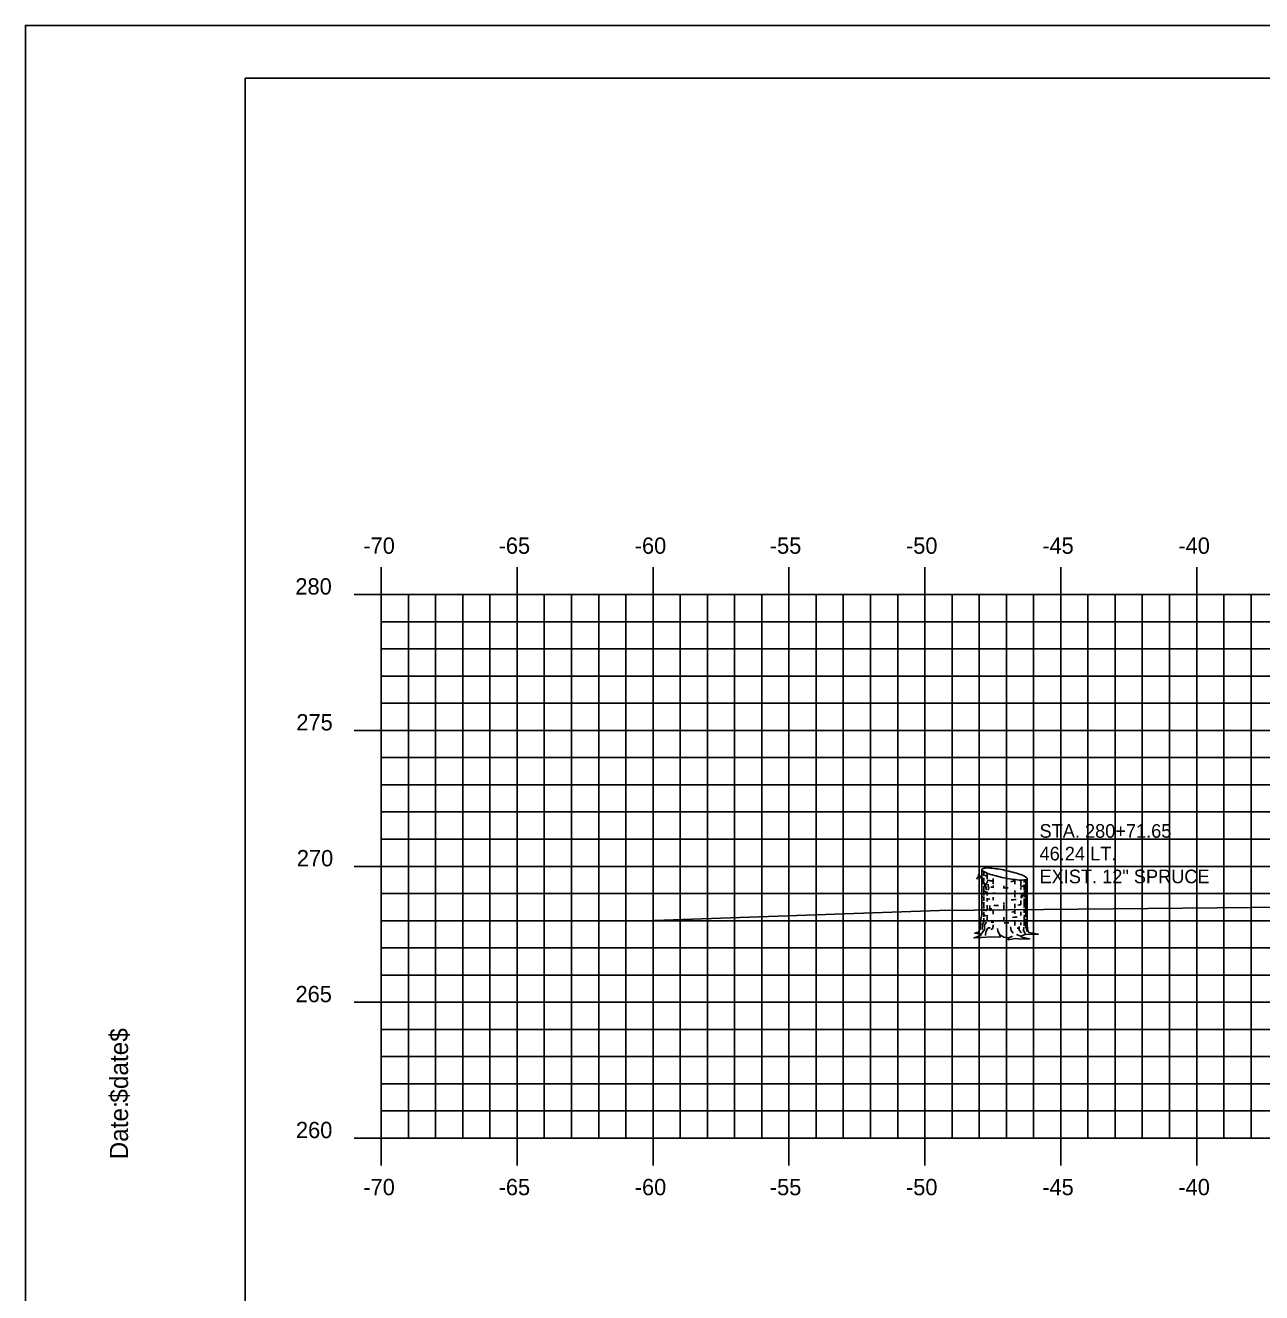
# Model space of a CAD drawing. Extents: x 855121 to 855291, y 366268 to 366378.
# Drawn here: x 855121.35 to 855166.83, y 366331.55 to 366378.18 of the extents above; entities that cross this region are included whole.
import ezdxf

# ---------------------------------------------------------------- set-up
doc = ezdxf.new("R2010")
doc.units = 0
for name, color, linetype in [('BORDER', 7, 'Continuous'), ('D_Text_Monospaced', 7, 'Continuous'), ('H_V ANNOTATION', 7, 'Continuous'), ('MAJOR', 7, 'Continuous'), ('MINOR', 7, 'Continuous'), ('PLOT BOUNDARY', 7, 'Continuous'), ('S_Roadway_Centerline', 7, 'Continuous'), ('S_Trees_Conifer_Pay', 7, 'Continuous')]:
    doc.layers.add(name, color=color, linetype=linetype)

msp = doc.modelspace()

# ---------------------------------------------------------------- linework, layer by layer
at = {"layer": 'BORDER'}
for p, q in [((855289.442, 366376.236), (855129.442, 366376.236)), ((855129.442, 366376.236), (855129.442, 366271.236))]:
    msp.add_line(p, q, dxfattribs=at)
at = {"layer": 'MAJOR'}
for p, q in [((855134.442, 366358.238), (855134.442, 366357.236)), ((855139.442, 366358.238), (855139.442, 366357.236)), ((855144.442, 366358.238), (855144.442, 366357.236)), ((855149.442, 366358.238), (855149.442, 366357.236)), ((855154.442, 366358.238), (855154.442, 366357.236)), ((855159.442, 366358.238), (855159.442, 366357.236)), ((855164.442, 366358.238), (855164.442, 366357.236)), ((855133.44, 366357.236), (855134.442, 366357.236)), ((855134.442, 366357.236), (855274.442, 366357.236)), ((855134.442, 366337.236), (855134.442, 366357.236)), ((855134.442, 366337.236), (855134.442, 366357.236)), ((855134.442, 366357.236), (855274.442, 366357.236)), ((855139.442, 366337.236), (855139.442, 366357.236)), ((855144.442, 366337.236), (855144.442, 366357.236)), ((855149.442, 366337.236), (855149.442, 366357.236)), ((855154.442, 366337.236), (855154.442, 366357.236)), ((855159.442, 366337.236), (855159.442, 366357.236)), ((855164.442, 366337.236), (855164.442, 366357.236)), ((855133.44, 366352.236), (855134.442, 366352.236)), ((855134.442, 366352.236), (855274.442, 366352.236)), ((855133.44, 366347.236), (855134.442, 366347.236)), ((855134.442, 366347.236), (855274.442, 366347.236)), ((855133.44, 366342.236), (855134.442, 366342.236)), ((855134.442, 366342.236), (855274.442, 366342.236)), ((855133.44, 366337.236), (855134.442, 366337.236)), ((855134.442, 366337.236), (855274.442, 366337.236)), ((855134.442, 366337.236), (855274.442, 366337.236)), ((855134.442, 366336.234), (855134.442, 366337.236)), ((855139.442, 366336.234), (855139.442, 366337.236)), ((855144.442, 366336.234), (855144.442, 366337.236)), ((855149.442, 366336.234), (855149.442, 366337.236)), ((855154.442, 366336.234), (855154.442, 366337.236)), ((855159.442, 366336.234), (855159.442, 366337.236)), ((855164.442, 366336.234), (855164.442, 366337.236))]:
    msp.add_line(p, q, dxfattribs=at)
at = {"layer": 'MINOR'}
for p, q in [((855135.442, 366337.236), (855135.442, 366357.236)), ((855136.442, 366337.236), (855136.442, 366357.236)), ((855137.442, 366337.236), (855137.442, 366357.236)), ((855138.442, 366337.236), (855138.442, 366357.236)), ((855140.442, 366337.236), (855140.442, 366357.236)), ((855141.442, 366337.236), (855141.442, 366357.236)), ((855142.442, 366337.236), (855142.442, 366357.236)), ((855143.442, 366337.236), (855143.442, 366357.236)), ((855145.442, 366337.236), (855145.442, 366357.236)), ((855146.442, 366337.236), (855146.442, 366357.236)), ((855147.442, 366337.236), (855147.442, 366357.236)), ((855148.442, 366337.236), (855148.442, 366357.236)), ((855150.442, 366337.236), (855150.442, 366357.236)), ((855151.442, 366337.236), (855151.442, 366357.236)), ((855152.442, 366337.236), (855152.442, 366357.236)), ((855153.442, 366337.236), (855153.442, 366357.236)), ((855155.442, 366337.236), (855155.442, 366357.236)), ((855156.442, 366337.236), (855156.442, 366357.236)), ((855157.442, 366337.236), (855157.442, 366357.236)), ((855158.442, 366337.236), (855158.442, 366357.236)), ((855160.442, 366337.236), (855160.442, 366357.236)), ((855161.442, 366337.236), (855161.442, 366357.236)), ((855162.442, 366337.236), (855162.442, 366357.236)), ((855163.442, 366337.236), (855163.442, 366357.236)), ((855165.442, 366337.236), (855165.442, 366357.236)), ((855166.442, 366337.236), (855166.442, 366357.236)), ((855134.442, 366356.236), (855274.442, 366356.236)), ((855134.442, 366356.236), (855135.444, 366356.236)), ((855134.442, 366355.236), (855274.442, 366355.236)), ((855134.442, 366355.236), (855135.444, 366355.236)), ((855134.442, 366354.236), (855274.442, 366354.236)), ((855134.442, 366354.236), (855135.444, 366354.236)), ((855134.442, 366353.236), (855274.442, 366353.236)), ((855134.442, 366353.236), (855135.444, 366353.236)), ((855134.442, 366351.236), (855274.442, 366351.236)), ((855134.442, 366351.236), (855135.444, 366351.236)), ((855134.442, 366350.236), (855274.442, 366350.236)), ((855134.442, 366350.236), (855135.444, 366350.236)), ((855134.442, 366349.236), (855274.442, 366349.236)), ((855134.442, 366349.236), (855135.444, 366349.236)), ((855134.442, 366348.236), (855135.444, 366348.236)), ((855134.442, 366348.236), (855274.442, 366348.236)), ((855134.442, 366346.236), (855274.442, 366346.236)), ((855134.442, 366346.236), (855135.444, 366346.236)), ((855134.442, 366345.236), (855274.442, 366345.236)), ((855134.442, 366345.236), (855135.444, 366345.236)), ((855134.442, 366344.236), (855274.442, 366344.236)), ((855134.442, 366344.236), (855135.444, 366344.236)), ((855134.442, 366343.236), (855274.442, 366343.236)), ((855134.442, 366343.236), (855135.444, 366343.236)), ((855134.442, 366341.236), (855274.442, 366341.236)), ((855134.442, 366341.236), (855135.444, 366341.236)), ((855134.442, 366340.236), (855274.442, 366340.236)), ((855134.442, 366340.236), (855135.444, 366340.236)), ((855134.442, 366339.236), (855274.442, 366339.236)), ((855134.442, 366339.236), (855135.444, 366339.236)), ((855134.442, 366338.236), (855274.442, 366338.236)), ((855134.442, 366338.236), (855135.444, 366338.236))]:
    msp.add_line(p, q, dxfattribs=at)
at = {"layer": 'PLOT BOUNDARY'}
msp.add_lwpolyline([(855121.349, 366268.177), (855291.349, 366268.177), (855291.349, 366378.177), (855121.349, 366378.177)], close=True, dxfattribs=at)
at = {"layer": 'S_Roadway_Centerline'}
msp.add_lwpolyline([(855144.138, 366345.236), (855154.981, 366345.612), (855167.747, 366345.731), (855178.089, 366345.883), (855179.388, 366345.897), (855182.154, 366346.026), (855184.948, 366346.054), (855186.531, 366346.008), (855186.852, 366345.93), (855188.684, 366345.832), (855189.07, 366345.851), (855194.05, 366346.181), (855199.995, 366346.43), (855204.747, 366346.643), (855214.965, 366346.488), (855215.768, 366346.474), (855220.431, 366346.316), (855220.775, 366346.323), (855220.997, 366346.289), (855221.747, 366346.285), (855225.306, 366346.406), (855236.796, 366346.885)], dxfattribs=at)
at = {"layer": 'S_Trees_Conifer_Pay'}
for p, q in [((855156.54, 366345.473), (855156.54, 366347.12)), ((855156.611, 366347.048), (855156.611, 366346.885)), ((855156.611, 366346.818), (855156.611, 366346.69)), ((855156.729, 366346.987), (855156.729, 366346.764)), ((855156.729, 366346.675), (855156.729, 366346.628)), ((855156.957, 366346.791), (855156.957, 366346.591)), ((855157.753, 366346.749), (855157.753, 366346.581)), ((855157.973, 366346.728), (855157.973, 366346.496)), ((855158.098, 366346.736), (855158.098, 366346.638)), ((855158.098, 366346.564), (855158.098, 366346.36)), ((855158.156, 366346.747), (855158.156, 366346.276)), ((855158.204, 366345.063), (855158.204, 366346.785)), ((855156.611, 366346.503), (855156.611, 366346.167)), ((855156.611, 366346.13), (855156.611, 366345.967)), ((855156.671, 366346.492), (855156.723, 366346.432)), ((855156.729, 366346.293), (855156.729, 366346.161)), ((855156.957, 366346.533), (855156.957, 366346.445)), ((855156.957, 366346.097), (855156.957, 366345.992)), ((855157.347, 366346.517), (855157.347, 366346.422)), ((855157.753, 366346.344), (855157.753, 366346.107)), ((855157.973, 366346.455), (855157.973, 366346.381)), ((855158.098, 366346.302), (855158.098, 366346.103)), ((855158.156, 366346.212), (855158.156, 366345.904)), ((855156.611, 366345.92), (855156.611, 366345.703)), ((855156.611, 366345.673), (855156.611, 366345.598)), ((855156.729, 366346.05), (855156.729, 366345.94)), ((855156.729, 366345.804), (855156.729, 366345.663)), ((855156.957, 366345.625), (855156.957, 366345.479)), ((855157.347, 366345.904), (855157.347, 366345.829)), ((855157.347, 366345.804), (855157.347, 366345.656)), ((855157.753, 366345.862), (855157.753, 366345.71)), ((855157.753, 366345.667), (855157.753, 366345.493)), ((855157.973, 366345.978), (855157.973, 366345.839)), ((855158.098, 366346.056), (855158.098, 366345.72)), ((855158.098, 366345.667), (855158.098, 366345.531)), ((855158.156, 366345.856), (855158.156, 366345.364)), ((855156.611, 366345.558), (855156.611, 366345.384)), ((855156.729, 366345.436), (855156.729, 366345.263)), ((855156.957, 366345.247), (855156.957, 366345.158)), ((855157.347, 366345.364), (855157.347, 366345.211)), ((855157.753, 366345.216), (855157.753, 366345.063)), ((855157.973, 366345.568), (855157.973, 366345.426)), ((855157.973, 366345.164), (855157.973, 366345.07)), ((855158.098, 366345.432), (855158.098, 366345.053)), ((855158.156, 366345.31), (855158.156, 366345.063)), ((855157.973, 366344.67), (855157.81, 366344.734)), ((855157.536, 366344.606), (855157.662, 366344.67))]:
    msp.add_line(p, q, dxfattribs=at)
for points in [[(855156.494, 366346.851), (855156.418, 366346.859), (855156.346, 366346.76)], [(855156.723, 366346.618), (855156.686, 366346.544), (855156.639, 366346.601), (855156.581, 366346.669), (855156.488, 366346.863), (855156.424, 366346.91), (855156.393, 366346.917)], [(855156.708, 366346.365), (855156.671, 366346.492), (855156.608, 366346.608), (855156.577, 366346.675), (855156.508, 366346.821)], [(855156.756, 366346.581), (855156.787, 366346.496), (855156.791, 366346.428), (855156.76, 366346.365)], [(855158.024, 366346.091), (855158.03, 366346.186), (855157.987, 366346.163), (855157.987, 366346.068)], [(855156.885, 366345.692), (855156.873, 366345.615), (855156.826, 366345.625), (855156.838, 366345.792)], [(855156.54, 366345.473), (855156.488, 366345.211), (855156.472, 366344.938), (855156.414, 366344.812), (855156.278, 366344.781), (855156.509, 366344.744), (855156.509, 366344.744), (855156.503, 366344.697), (855156.255, 366344.602), (855156.53, 366344.619), (855156.885, 366344.639), (855157.207, 366344.629), (855157.2, 366344.711), (855157.349, 366344.629), (855157.536, 366344.606), (855157.511, 366344.538), (855157.779, 366344.581), (855158, 366344.554), (855158.292, 366344.571), (855158.003, 366344.629), (855157.973, 366344.67), (855158.135, 366344.728), (855158.372, 366344.738), (855158.613, 366344.738), (855158.271, 366344.796), (855158.23, 366344.876), (855158.204, 366345.063)], [(855156.713, 366345.185), (855156.639, 366345.08), (855156.634, 366344.907), (855156.509, 366344.744)], [(855156.614, 366345.331), (855156.608, 366345.185), (855156.561, 366345.117), (855156.55, 366344.917)], [(855156.671, 366344.691), (855156.686, 366344.829), (855156.76, 366344.958)], [(855156.95, 366345.08), (855156.939, 366344.954), (855156.865, 366344.911)], [(855157.2, 366344.711), (855157.126, 366344.853), (855157.116, 366344.954)], [(855157.689, 366344.781), (855157.621, 366344.876), (855157.594, 366345.016)], [(855157.915, 366345.022), (855157.915, 366344.89), (855158.003, 366344.791)], [(855158.078, 366344.995), (855158.072, 366344.88), (855158.125, 366344.791), (855158.135, 366344.728)], [(855158.156, 366345.016), (855158.177, 366344.938), (855158.197, 366344.843)]]:
    msp.add_lwpolyline(points, dxfattribs=at)
for centre, radius, start, end in [((855156.562, 366347.12), 0.0226, 168.2806, 179.9685), ((855156.566, 366347.12), 0.0264, 179.9685, 190.7806), ((855156.562, 366347.12), 0.0226, 156.5926, 168.2806), ((855156.571, 366347.121), 0.0314, 190.7806, 203.4842), ((855156.566, 366347.119), 0.0264, 145.7806, 156.5926), ((855156.59, 366347.13), 0.0527, 203.4842, 213.2806), ((855156.57, 366347.116), 0.0314, 133.077, 145.7806), ((855156.615, 366347.146), 0.0817, 213.2806, 227.6113), ((855156.584, 366347.1), 0.0527, 123.2806, 133.077), ((855156.6, 366347.076), 0.0817, 108.9499, 123.2806), ((855156.728, 366347.27), 0.251, 227.6113, 235.7806), ((855156.655, 366346.916), 0.251, 100.7806, 108.9499), ((855157.038, 366347.726), 0.802, 235.7806, 251.9406), ((855156.758, 366346.375), 0.802, 84.6206, 100.7806), ((855156.348, 366342.017), 5.179, 78.2806, 84.6206), ((855156.348, 366342.017), 5.179, 71.9406, 78.2806), ((855156.573, 366346.994), 0.0334, 185.7849, 196.0515), ((855156.573, 366346.839), 0.0334, 185.7849, 196.0515), ((855156.583, 366346.997), 0.0441, 196.0515, 210), ((855156.583, 366346.842), 0.0441, 196.0515, 210), ((855156.599, 366347.006), 0.0624, 210, 228.7494), ((855156.599, 366346.851), 0.0624, 210, 228.7494), ((855156.671, 366347.089), 0.172, 228.7494, 240), ((855156.671, 366346.934), 0.172, 228.7494, 240), ((855156.87, 366347.279), 0.571, 240, 242.9763), ((855156.87, 366347.434), 0.571, 247.5868, 255.5683), ((855156.87, 366347.279), 0.571, 255.6333, 261.8968), ((855158.395, 366351.887), 5.179, 251.9406, 258.2806), ((855157.371, 366350.797), 4.124, 261.8968, 263.762), ((855158.395, 366351.887), 5.179, 258.2806, 264.6206), ((855157.371, 366350.797), 4.124, 273.2669, 275.3045), ((855157.985, 366347.53), 0.802, 264.6206, 280.7806), ((855157.705, 366346.179), 0.802, 55.7806, 71.9406), ((855158.088, 366346.988), 0.251, 280.7806, 288.9499), ((855158.015, 366346.634), 0.251, 47.6113, 55.7806), ((855157.874, 366347.046), 0.571, 299.6633, 300), ((855158.073, 366346.701), 0.172, 300, 311.2506), ((855158.143, 366346.829), 0.0817, 288.9499, 303.2806), ((855158.128, 366346.759), 0.0817, 33.2806, 47.6113), ((855158.145, 366346.619), 0.0624, 311.2506, 330), ((855158.159, 366346.804), 0.0527, 303.2806, 313.077), ((855158.173, 366346.789), 0.0314, 313.077, 325.7806), ((855158.153, 366346.775), 0.0527, 23.4842, 33.2806), ((855158.177, 366346.786), 0.0264, 325.7806, 336.5926), ((855158.161, 366346.609), 0.0441, 330, 343.9485), ((855158.172, 366346.784), 0.0314, 10.7806, 23.4842), ((855158.181, 366346.784), 0.0226, 336.5926, 348.2806), ((855158.177, 366346.784), 0.0264, 359.9685, 10.7806), ((855158.181, 366346.784), 0.0226, 348.2806, 359.9685), ((855158.171, 366346.606), 0.0334, 0, 16.0515), ((855158.171, 366346.606), 0.0334, 343.9485, 360), ((855156.573, 366346.395), 0.0334, 185.7849, 196.0515), ((855156.574, 366346.16), 0.0334, 185.7849, 196.0515), ((855156.584, 366346.163), 0.0441, 196.0515, 210), ((855156.6, 366346.172), 0.0624, 210, 228.7494), ((855156.673, 366346.254), 0.172, 228.7494, 240), ((855156.872, 366346.599), 0.571, 240, 242.8104), ((855156.871, 366346.835), 0.571, 242.9571, 255.5507), ((855157.373, 366350.564), 4.124, 262.9442, 264.2151), ((855157.371, 366350.353), 4.124, 264.0496, 266.2948), ((855157.373, 366350.564), 4.124, 269.6419, 270), ((855157.373, 366350.564), 4.124, 270, 271.9249), ((855157.874, 366347.046), 0.571, 282.0154, 293.1403), ((855157.872, 366346.835), 0.571, 292.9413, 300), ((855157.874, 366346.599), 0.571, 299.6633, 300), ((855158.073, 366346.254), 0.172, 300, 311.2506), ((855158.145, 366346.172), 0.0624, 311.2506, 330), ((855158.161, 366346.163), 0.0441, 330, 343.9485), ((855158.171, 366346.16), 0.0334, 0, 16.0515), ((855158.171, 366346.16), 0.0334, 343.9485, 360), ((855156.574, 366345.95), 0.0334, 185.7849, 196.0515), ((855156.584, 366345.953), 0.0441, 196.0515, 210), ((855156.6, 366345.962), 0.0624, 210, 228.7494), ((855156.673, 366346.044), 0.172, 228.7494, 240), ((855156.872, 366346.389), 0.571, 240, 242.8104), ((855156.872, 366346.153), 0.571, 242.8104, 254.6017), ((855156.872, 366346.599), 0.571, 253.0704, 261.8968), ((855157.373, 366350.117), 4.124, 261.8968, 262.3875), ((855157.373, 366349.907), 4.124, 264.5431, 266.8507), ((855157.373, 366349.907), 4.124, 269.6419, 270), ((855157.373, 366350.117), 4.124, 273.3324, 275.919), ((855157.373, 366349.907), 4.124, 276.8526, 278.1032), ((855157.874, 366346.389), 0.571, 278.1032, 280.7293), ((855157.874, 366346.389), 0.571, 293.1403, 300), ((855157.874, 366346.153), 0.571, 293.1403, 300), ((855158.073, 366346.044), 0.172, 300, 311.2506), ((855158.073, 366345.808), 0.172, 300, 311.2506), ((855158.145, 366345.962), 0.0624, 311.2506, 330), ((855158.145, 366345.725), 0.0624, 311.2506, 330), ((855158.161, 366345.953), 0.0441, 330, 343.9485), ((855158.161, 366345.716), 0.0441, 330, 343.9485), ((855158.171, 366345.95), 0.0334, 0, 16.0515), ((855158.171, 366345.95), 0.0334, 343.9485, 360), ((855158.171, 366345.713), 0.0334, 0, 16.0515), ((855158.171, 366345.713), 0.0334, 343.9485, 360), ((855156.574, 366345.515), 0.0334, 185.7849, 196.0515), ((855156.584, 366345.518), 0.0441, 196.0515, 210), ((855156.6, 366345.527), 0.0624, 210, 228.7494), ((855156.673, 366345.61), 0.172, 228.7494, 240), ((855156.872, 366345.955), 0.571, 240, 250.7093), ((855156.872, 366345.759), 0.571, 242.7279, 251.4933), ((855157.373, 366349.277), 4.124, 263.2104, 264.2151), ((855157.373, 366349.277), 4.124, 269.8672, 270), ((855157.373, 366349.277), 4.124, 270, 272.1883), ((855157.373, 366349.67), 4.124, 273.6807, 275.284), ((855157.373, 366349.473), 4.124, 274.1603, 276.5009), ((855157.884, 366345.961), 0.571, 291.9732, 298.7631), ((855157.874, 366345.759), 0.571, 293.1403, 300), ((855158.073, 366345.414), 0.172, 300, 311.2506), ((855158.145, 366345.332), 0.0624, 311.2506, 330), ((855158.161, 366345.323), 0.0441, 330, 343.9485), ((855158.171, 366345.515), 0.0334, 0, 16.0515), ((855158.171, 366345.32), 0.0334, 0, 16.0515), ((855158.171, 366345.32), 0.0334, 343.9485, 360), ((855156.574, 366345.099), 0.0334, 185.7849, 196.0515), ((855156.584, 366345.102), 0.0441, 196.0515, 210), ((855156.6, 366345.111), 0.0624, 210, 228.7494), ((855156.673, 366345.194), 0.172, 228.7494, 240), ((855156.872, 366345.539), 0.571, 258.363, 261.8968), ((855157.373, 366349.057), 4.124, 261.8968, 262.6316), ((855157.373, 366349.057), 4.124, 276.488, 277.5562), ((855157.874, 366345.539), 0.571, 295.4686, 300), ((855158.073, 366345.194), 0.172, 300, 311.2506), ((855158.145, 366345.111), 0.0624, 311.2506, 330), ((855158.161, 366345.102), 0.0441, 330, 343.9485), ((855158.171, 366345.099), 0.0334, 0, 16.0515), ((855158.171, 366345.099), 0.0334, 343.9485, 360)]:
    msp.add_arc(centre, radius, start, end, dxfattribs=at)

# ---------------------------------------------------------------- texts
at = {"layer": 'BORDER'}
for s, p in [('$date$', (855125.127, 366338.542)), ('Date:', (855125.127, 366336.453))]:
    msp.add_text(s, height=0.6696, rotation=90, dxfattribs=at).set_placement(p)
at = {"layer": 'D_Text_Monospaced'}
for s, height, p in [('STA. 280+71.65', 0.49998, (855158.661, 366348.288)), ('46.24 LT.', 0.5, (855158.661, 366347.454)), ('EXIST. 12" SPRUCE', 0.49998, (855158.661, 366346.614))]:
    msp.add_text(s, height=height, dxfattribs=at).set_placement(p)
at = {"layer": 'H_V ANNOTATION'}
for s, p in [('-70', (855133.783, 366358.736)), ('-65', (855138.76, 366358.736)), ('-60', (855143.768, 366358.736)), ('-55', (855148.738, 366358.736)), ('-50', (855153.746, 366358.736)), ('-45', (855158.76, 366358.736)), ('-40', (855163.768, 366358.736)), ('280', (855131.283, 366357.236)), ('275', (855131.32, 366352.236)), ('270', (855131.336, 366347.236)), ('265', (855131.288, 366342.236)), ('260', (855131.304, 366337.236)), ('-70', (855133.783, 366335.136)), ('-65', (855138.76, 366335.136)), ('-60', (855143.768, 366335.136)), ('-55', (855148.738, 366335.136)), ('-50', (855153.746, 366335.136)), ('-45', (855158.76, 366335.136)), ('-40', (855163.768, 366335.136))]:
    msp.add_text(s, height=0.6, dxfattribs=at).set_placement(p)

doc.saveas('drawing.dxf')
